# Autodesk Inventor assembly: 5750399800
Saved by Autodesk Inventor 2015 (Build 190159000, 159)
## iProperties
Created: 2020-07
Part Number: 5750399800
Checked By: TraceParts S.A.
Catalog Web Link: www.traceparts.com
Document SubType Name: Assembly
Designer: TraceParts
Company: TraceParts S.A.
Author: TraceParts
REFERENCE: 5750399800
DESIGN: HXBR-200 ECOWATT (230V50/60Hz) VE - 5750399800
SUPPLIER: Soler & Palau
TraceParts.PartNumber: 10-20122018-119605
TraceParts.PartTitle: HXBR-ECOWATT
TraceParts.InstanceId: 10-20122018-11960511ZZJMS0BA5QAJ4JJLZQP8YGF
TraceParts.PartStatus: Published
TraceParts.PartVersion: 1.0.2
TRACEPARTS: TRACEPARTS
TraceParts.PartLanguage: en
TraceParts.ClassPath: SOLER_PALAU:10-20122018-119605
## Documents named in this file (3)
- C:\TPO v2\SharedFS\Outgoing\5750399800.iam
- C:\TPO v2\SharedFS\Outgoing\5750399800_01.ipt
- C:\TPO v2\SharedFS\Outgoing\5750399800_02.ipt
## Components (2 placed, 2 different names)
1. 5750399800_01:1
2. 5750399800_02:1
